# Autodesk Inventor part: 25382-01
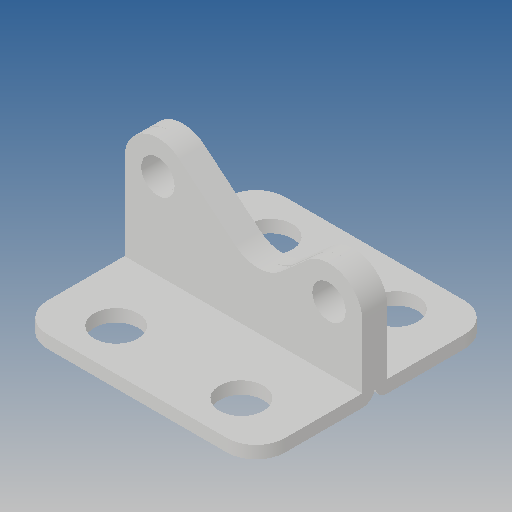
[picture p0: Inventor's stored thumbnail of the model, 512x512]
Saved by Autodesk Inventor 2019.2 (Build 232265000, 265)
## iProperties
Created: 2012-09
Part Number: 25382-01
Material: Ogólny
Document SubType Name: Modeling
Designer: CADENGINEERING4
Density: 1 g/cm^3
Appearance: Domyślna
Author: CADENGINEERING4
Revision Number: ÈÎºÎ
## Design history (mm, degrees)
feature "Ô²½Ç1"
feature "¾µÏò1"
node "Bryła1"
node "Bryła2"
